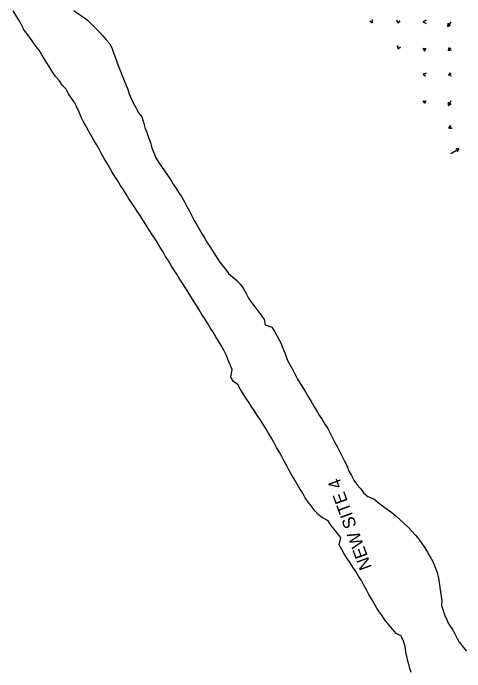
# Model space of a CAD drawing. Extents: x 954385 to 988206, y 1868364 to 1924553.
# Drawn here: x 955775 to 956634, y 1920383 to 1921635 of the extents above; entities that cross this region are included whole.
import ezdxf

# ---------------------------------------------------------------- set-up
doc = ezdxf.new("R2010")
doc.units = 0
for name, color, linetype in [('31', 7, 'Continuous'), ('Perimeter', 7, 'Continuous'), ('Slopes', 7, 'Continuous')]:
    doc.layers.add(name, color=color, linetype=linetype)

msp = doc.modelspace()

# ---------------------------------------------------------------- linework, layer by layer
at = {"layer": 'Perimeter'}
for points in [[(956531.6, 1920381.8), (956528.8, 1920389.4), (956526.2, 1920399.6), (956525.2, 1920403.5), (956523.6, 1920409.8), (956521.2, 1920420.1), (956520.5, 1920426.4), (956520.2, 1920431.4), (956517.2, 1920441.3), (956514, 1920448.1), (956513, 1920450.5), (956502.9, 1920456), (956496.8, 1920463.2), (956496.3, 1920463.8), (956489.6, 1920471.5), (956483.3, 1920479.4), (956482.7, 1920480.2), (956477.4, 1920487.5), (956471.8, 1920495.9), (956470.2, 1920498.2), (956466.4, 1920504.3), (956461.1, 1920512.8), (956456.1, 1920521.5), (956451.3, 1920530.2), (956446.5, 1920539), (956441.8, 1920547.9), (956437.1, 1920556.8), (956431.6, 1920565.1), (956426.1, 1920573.5), (956420.8, 1920581.9), (956415.3, 1920590.3), (956409.8, 1920598.7), (956404.4, 1920607.1), (956399.5, 1920615.8), (956394.7, 1920624.6), (956397.8, 1920638.2), (956391.4, 1920646), (956385.3, 1920654), (956378.5, 1920661.6), (956373.4, 1920670.1), (956363.1, 1920675.6), (956354.4, 1920682), (956347.9, 1920689.7), (956341.7, 1920697.7), (956335.4, 1920705.5), (956330.2, 1920714.1), (956325.2, 1920722.8), (956319.9, 1920731.2), (956314.9, 1920739.9), (956309.9, 1920748.5), (956304.8, 1920757.2), (956299.6, 1920765.7), (956294.9, 1920774.5), (956290.2, 1920783.4), (956285.5, 1920792.2), (956280.6, 1920801), (956275.7, 1920809.7), (956270.7, 1920818.3), (956265.7, 1920827), (956260.6, 1920835.6), (956255.5, 1920844.2), (956250.5, 1920852.9), (956245.1, 1920861.3), (956239.3, 1920869.5), (956234, 1920877.9), (956228.6, 1920886.4), (956223.1, 1920894.7), (956217.5, 1920903), (956212.2, 1920911.5), (956207.1, 1920920.1), (956202.2, 1920928.8), (956193.6, 1920935.3), (956189.4, 1920942.1), (956188.4, 1920943.8), (956191.3, 1920957.4), (956191.2, 1920957.9), (956188.2, 1920965.3), (956187.5, 1920966.7), (956183.3, 1920975.9), (956181.9, 1920979.6), (956179.8, 1920985.5), (956175.4, 1920994.5), (956170.4, 1921003.2), (956165.2, 1921011.7), (956159.9, 1921020.2), (956154.7, 1921028.7), (956149.5, 1921037.3), (956144.2, 1921045.8), (956138.9, 1921054.3), (956133.6, 1921062.7), (956128.4, 1921071.3), (956123.3, 1921079.5), (956117.8, 1921088.2), (956112.5, 1921096.7), (956107.1, 1921105.1), (956101.8, 1921113.6), (956096.4, 1921122), (956091.1, 1921130.5), (956085.7, 1921138.9), (956080.4, 1921147.4), (956075.1, 1921155.9), (956069.8, 1921164.3), (956064.5, 1921172.8), (956059.7, 1921181.6), (956054.4, 1921190.1), (956049.1, 1921198.6), (956043.7, 1921207), (956038.3, 1921215.4), (956032.8, 1921223.8), (956027.5, 1921232.3), (956022.3, 1921240.8), (956016.8, 1921249.2), (956011.3, 1921257.5), (956006, 1921266), (956000.1, 1921274.1), (955994.7, 1921282.6), (955989.6, 1921291.1), (955984.2, 1921299.6), (955978.8, 1921308), (955973.4, 1921316.4), (955968, 1921324.8), (955962.7, 1921333.3), (955957.6, 1921341.9), (955952.9, 1921350.7), (955947.8, 1921359.3), (955942.7, 1921368), (955937.9, 1921376.7), (955933, 1921385.4), (955928, 1921394.1), (955923, 1921402.8), (955918.1, 1921411.5), (955913.2, 1921420.2), (955908.3, 1921429), (955903.9, 1921438), (955899.9, 1921447.3), (955895.6, 1921456.4), (955891.1, 1921465.3), (955885.4, 1921473.6), (955880, 1921482), (955875.4, 1921490.9), (955868.1, 1921498.2), (955862.5, 1921506.5), (955855.9, 1921514.1), (955850.3, 1921522.4), (955844.9, 1921530.9), (955839.7, 1921539.4), (955834.3, 1921547.8), (955829, 1921556.3), (955824.2, 1921565.1), (955817.7, 1921572.8), (955811.8, 1921581), (955806, 1921589.1), (955800.1, 1921597.2), (955794.4, 1921605.1), (955794.2, 1921605.4), (955789.8, 1921614.4), (955785, 1921623.2), (955779.8, 1921631.7), (955774.6, 1921640.2)], [(955890, 1921640.5), (955899, 1921634.3), (955908.1, 1921628.1), (955916.3, 1921621.4), (955923.7, 1921614.3), (955931.1, 1921607.1), (955934, 1921604.1), (955938.2, 1921599.7), (955945, 1921592.1), (955951.7, 1921584.5), (955958.6, 1921577), (955962.8, 1921567.8), (955966.2, 1921558.2), (955969.6, 1921548.6), (955973.3, 1921539.1), (955977.1, 1921529.7), (955980.9, 1921520.3), (955984.6, 1921510.9), (955988.2, 1921501.3), (955991.9, 1921491.9), (955995.3, 1921482.2), (955999.2, 1921472.9), (956003.3, 1921463.6), (956008.2, 1921454.9), (956012.9, 1921446.1), (956019, 1921438.1), (956022.2, 1921428.3), (956024.8, 1921418.2), (956028.6, 1921408.8), (956032.2, 1921399.2), (956035.7, 1921389.7), (956038.3, 1921379.5), (956042, 1921370.1), (956045.7, 1921360.6), (956051, 1921352.2), (956056.8, 1921344), (956062.4, 1921335.7), (956068, 1921327.4), (956073.5, 1921319.1), (956079, 1921310.6), (956084.4, 1921302.2), (956089.8, 1921293.8), (956095.2, 1921285.4), (956100.3, 1921276.8), (956105.1, 1921268.1), (956109.8, 1921259.2), (956114.4, 1921250.3), (956119.1, 1921241.5), (956124, 1921232.7), (956128.8, 1921223.9), (956133.8, 1921215.2), (956139, 1921206.7), (956144.2, 1921198.2), (956149.6, 1921189.7), (956155, 1921181.3), (956160.4, 1921172.9), (956165.8, 1921164.5), (956171.8, 1921156.4), (956178.2, 1921148.6), (956183.9, 1921140.4), (956192.2, 1921133.7), (956200.2, 1921126.9), (956200.4, 1921126.7), (956207, 1921119.4), (956212.5, 1921111), (956217.5, 1921102.3), (956222.4, 1921093.6), (956228, 1921085.3), (956234, 1921077.2), (956240.2, 1921069.3), (956246.1, 1921061.2), (956251.7, 1921052.9), (956254.1, 1921042.7), (956266.6, 1921038.6), (956269.9, 1921033.5), (956271.7, 1921030), (956276.4, 1921021.2), (956277.2, 1921019.8), (956281.2, 1921013), (956281.5, 1921012.5), (956285.4, 1921003.2), (956286.2, 1921001.3), (956289.6, 1920994), (956293.1, 1920984.5), (956296.6, 1920974.9), (956301.5, 1920966.2), (956306.3, 1920957.4), (956310.9, 1920948.5), (956315.6, 1920939.6), (956320.7, 1920931), (956325.9, 1920922.5), (956331.1, 1920913.9), (956336.4, 1920905.4), (956341.5, 1920896.8), (956346.5, 1920888.2), (956351.6, 1920879.6), (956356.7, 1920871), (956362.1, 1920862.6), (956367.4, 1920854.1), (956373.1, 1920845.9), (956377.2, 1920836.6), (956381.9, 1920827.8), (956386.4, 1920818.8), (956391.2, 1920810), (956395.9, 1920801.2), (956400.4, 1920792.2), (956405, 1920783.3), (956409.5, 1920774.3), (956413, 1920764.7), (956417.9, 1920756), (956422.7, 1920747.3), (956428.2, 1920738.9), (956435.2, 1920731.4), (956440.7, 1920723.1), (956449.3, 1920716.6), (956460.7, 1920711.9), (956468.8, 1920705.1), (956477, 1920698.4), (956485.8, 1920692.1), (956494.6, 1920685.7), (956502.9, 1920679.1), (956510.7, 1920672.1), (956518.2, 1920665), (956525.6, 1920657.8), (956532.9, 1920650.5), (956539.5, 1920642.8), (956546.2, 1920635.2), (956551.5, 1920626.7), (956557.8, 1920618.9), (956562.8, 1920610.2), (956567.7, 1920601.5), (956572.4, 1920592.6), (956576.5, 1920583.4), (956580.2, 1920574), (956582.3, 1920566.8), (956583, 1920564), (956584.9, 1920553.5), (956585.9, 1920543.6), (956586.1, 1920542.6), (956588.1, 1920532.1), (956589.5, 1920521.3), (956589.6, 1920520.4), (956588.9, 1920509.2), (956592.2, 1920499.6), (956593.1, 1920497.1), (956595.8, 1920490.1), (956599.7, 1920480.8), (956601.3, 1920476.7), (956604.3, 1920471.9), (956609.9, 1920463.7), (956612.9, 1920458.4), (956614.8, 1920455), (956619.3, 1920446.1), (956623.1, 1920439.1), (956623.2, 1920439.1), (956624.4, 1920437.5), (956630.5, 1920429.6), (956636.6, 1920422)]]:
    msp.add_lwpolyline(points, dxfattribs=at)
at = {"layer": 'Slopes'}
for points in [[(956457.1, 1921618.9), (956458.1, 1921617.1), (956453, 1921620.2), (956458.1, 1921617.1), (956458.2, 1921623.1)], [(956507.1, 1921618.9), (956506.8, 1921616.4), (956504.5, 1921621.9), (956506.8, 1921616.4), (956510.5, 1921621.1)], [(956557.1, 1921618.9), (956554.6, 1921618.9), (956559.8, 1921622), (956554.6, 1921618.9), (956559.9, 1921616)], [(956607.1, 1921618.9), (956601, 1921610.3), (956601.6, 1921616.3), (956601, 1921610.3), (956606.5, 1921612.8)], [(956507.1, 1921568.9), (956506.7, 1921567.8), (956505.7, 1921573.8), (956506.7, 1921567.8), (956511.4, 1921571.7)], [(956557.1, 1921568.9), (956556.7, 1921563.5), (956554.1, 1921568.9), (956556.7, 1921563.5), (956560.1, 1921568.5)], [(956607.1, 1921568.9), (956602.5, 1921564.3), (956604, 1921570.1), (956602.5, 1921564.3), (956608.3, 1921565.8)], [(956557.1, 1921518.9), (956554.3, 1921519.4), (956559.8, 1921521.6), (956554.3, 1921519.4), (956559, 1921515.6)], [(956607.1, 1921518.9), (956602.5, 1921517.3), (956606.4, 1921521.8), (956602.5, 1921517.3), (956608.4, 1921516.2)], [(956557.1, 1921468.9), (956557.4, 1921464), (956554.1, 1921469), (956557.4, 1921464), (956560.1, 1921469.3)], [(956607.1, 1921468.9), (956602.8, 1921460), (956602.4, 1921466), (956602.8, 1921460), (956607.8, 1921463.4)], [(956607.1, 1921418.9), (956603.2, 1921416.6), (956606.1, 1921421.8), (956603.2, 1921416.6), (956609.2, 1921416.6)], [(956607.1, 1921368.9), (956622.2, 1921377.5), (956619.2, 1921372.4), (956622.2, 1921377.5), (956616.2, 1921377.6)]]:
    msp.add_lwpolyline(points, dxfattribs=at)

# ---------------------------------------------------------------- texts
at = {"layer": '31'}
msp.add_text('NEW SITE 4', height=24, rotation=110, dxfattribs=at).set_placement((956457.1, 1920581.7))

doc.saveas('drawing.dxf')
